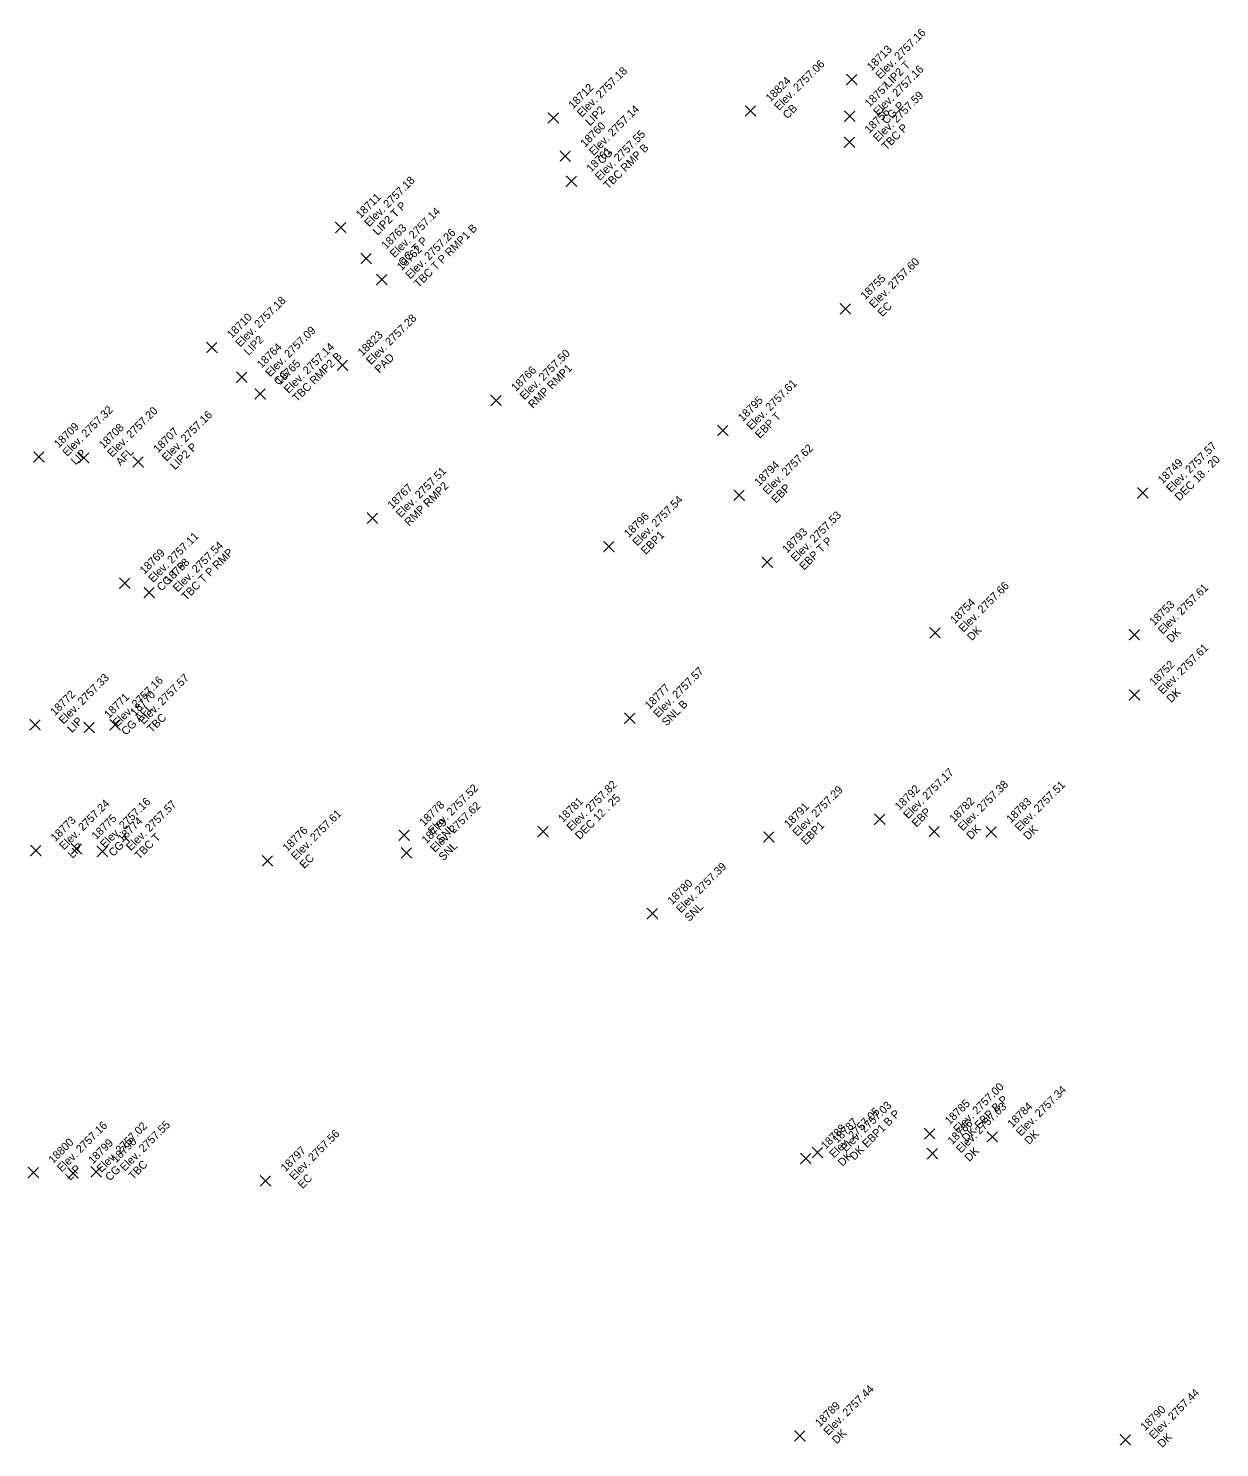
# Model space of a CAD drawing. Extents: x 2493999 to 2503109, y 700767 to 706646.
# Drawn here: x 2502305.46 to 2502341.16, y 700817.27 to 700859.84 of the extents above; entities that cross this region are included whole.
import ezdxf

# ---------------------------------------------------------------- set-up
doc = ezdxf.new("R2010")
doc.units = 0
doc.layers.add('ALG_CL_BLUE_Horiz', color=7, linetype='Continuous')
doc.layers.add('DES_SURFACE_Existing-Ground', color=7, linetype='Continuous')

msp = doc.modelspace()

# ---------------------------------------------------------------- linework, layer by layer
at = {"layer": 'ALG_CL_BLUE_Horiz'}
for points in [[(2502330.138, 700858.3), (2502329.988, 700858.45), (2502330.138, 700858.3), (2502329.988, 700858.15), (2502330.138, 700858.3), (2502330.288, 700858.15), (2502330.138, 700858.3), (2502330.288, 700858.45)], [(2502327.106, 700857.359), (2502326.956, 700857.509), (2502327.106, 700857.359), (2502326.956, 700857.209), (2502327.106, 700857.359), (2502327.256, 700857.209), (2502327.106, 700857.359), (2502327.256, 700857.509)], [(2502321.192, 700857.152), (2502321.042, 700857.302), (2502321.192, 700857.152), (2502321.042, 700857.002), (2502321.192, 700857.152), (2502321.342, 700857.002), (2502321.192, 700857.152), (2502321.342, 700857.302)], [(2502330.076, 700857.2), (2502329.926, 700857.35), (2502330.076, 700857.2), (2502329.926, 700857.05), (2502330.076, 700857.2), (2502330.226, 700857.05), (2502330.076, 700857.2), (2502330.226, 700857.35)], [(2502330.069, 700856.42), (2502329.919, 700856.57), (2502330.069, 700856.42), (2502329.919, 700856.27), (2502330.069, 700856.42), (2502330.219, 700856.27), (2502330.069, 700856.42), (2502330.219, 700856.57)], [(2502321.551, 700856.005), (2502321.401, 700856.155), (2502321.551, 700856.005), (2502321.401, 700855.855), (2502321.551, 700856.005), (2502321.701, 700855.855), (2502321.551, 700856.005), (2502321.701, 700856.155)], [(2502321.734, 700855.253), (2502321.584, 700855.403), (2502321.734, 700855.253), (2502321.584, 700855.103), (2502321.734, 700855.253), (2502321.884, 700855.103), (2502321.734, 700855.253), (2502321.884, 700855.403)], [(2502314.821, 700853.869), (2502314.671, 700854.019), (2502314.821, 700853.869), (2502314.671, 700853.719), (2502314.821, 700853.869), (2502314.971, 700853.719), (2502314.821, 700853.869), (2502314.971, 700854.019)], [(2502315.586, 700852.94), (2502315.436, 700853.09), (2502315.586, 700852.94), (2502315.436, 700852.79), (2502315.586, 700852.94), (2502315.736, 700852.79), (2502315.586, 700852.94), (2502315.736, 700853.09)], [(2502316.049, 700852.301), (2502315.899, 700852.451), (2502316.049, 700852.301), (2502315.899, 700852.151), (2502316.049, 700852.301), (2502316.199, 700852.151), (2502316.049, 700852.301), (2502316.199, 700852.451)], [(2502329.947, 700851.429), (2502329.797, 700851.579), (2502329.947, 700851.429), (2502329.797, 700851.279), (2502329.947, 700851.429), (2502330.097, 700851.279), (2502329.947, 700851.429), (2502330.097, 700851.579)], [(2502310.956, 700850.266), (2502310.806, 700850.416), (2502310.956, 700850.266), (2502310.806, 700850.116), (2502310.956, 700850.266), (2502311.106, 700850.116), (2502310.956, 700850.266), (2502311.106, 700850.416)], [(2502314.876, 700849.734), (2502314.726, 700849.884), (2502314.876, 700849.734), (2502314.726, 700849.584), (2502314.876, 700849.734), (2502315.026, 700849.584), (2502314.876, 700849.734), (2502315.026, 700849.884)], [(2502311.851, 700849.372), (2502311.701, 700849.522), (2502311.851, 700849.372), (2502311.701, 700849.222), (2502311.851, 700849.372), (2502312.001, 700849.222), (2502311.851, 700849.372), (2502312.001, 700849.522)], [(2502312.409, 700848.873), (2502312.259, 700849.023), (2502312.409, 700848.873), (2502312.259, 700848.723), (2502312.409, 700848.873), (2502312.559, 700848.723), (2502312.409, 700848.873), (2502312.559, 700849.023)], [(2502319.478, 700848.679), (2502319.328, 700848.829), (2502319.478, 700848.679), (2502319.328, 700848.529), (2502319.478, 700848.679), (2502319.628, 700848.529), (2502319.478, 700848.679), (2502319.628, 700848.829)], [(2502326.274, 700847.777), (2502326.124, 700847.927), (2502326.274, 700847.777), (2502326.124, 700847.627), (2502326.274, 700847.777), (2502326.424, 700847.627), (2502326.274, 700847.777), (2502326.424, 700847.927)], [(2502305.77, 700846.985), (2502305.62, 700847.135), (2502305.77, 700846.985), (2502305.62, 700846.835), (2502305.77, 700846.985), (2502305.92, 700846.835), (2502305.77, 700846.985), (2502305.92, 700847.135)], [(2502307.116, 700846.957), (2502306.966, 700847.107), (2502307.116, 700846.957), (2502306.966, 700846.807), (2502307.116, 700846.957), (2502307.266, 700846.807), (2502307.116, 700846.957), (2502307.266, 700847.107)], [(2502308.75, 700846.836), (2502308.6, 700846.986), (2502308.75, 700846.836), (2502308.6, 700846.686), (2502308.75, 700846.836), (2502308.9, 700846.686), (2502308.75, 700846.836), (2502308.9, 700846.986)], [(2502326.763, 700845.834), (2502326.613, 700845.984), (2502326.763, 700845.834), (2502326.613, 700845.684), (2502326.763, 700845.834), (2502326.913, 700845.684), (2502326.763, 700845.834), (2502326.913, 700845.984)], [(2502338.858, 700845.904), (2502338.708, 700846.054), (2502338.858, 700845.904), (2502338.708, 700845.754), (2502338.858, 700845.904), (2502339.008, 700845.754), (2502338.858, 700845.904), (2502339.008, 700846.054)], [(2502315.768, 700845.149), (2502315.618, 700845.299), (2502315.768, 700845.149), (2502315.618, 700844.999), (2502315.768, 700845.149), (2502315.918, 700844.999), (2502315.768, 700845.149), (2502315.918, 700845.299)], [(2502322.857, 700844.295), (2502322.707, 700844.445), (2502322.857, 700844.295), (2502322.707, 700844.145), (2502322.857, 700844.295), (2502323.007, 700844.145), (2502322.857, 700844.295), (2502323.007, 700844.445)], [(2502327.603, 700843.826), (2502327.453, 700843.976), (2502327.603, 700843.826), (2502327.453, 700843.676), (2502327.603, 700843.826), (2502327.753, 700843.676), (2502327.603, 700843.826), (2502327.753, 700843.976)], [(2502308.343, 700843.196), (2502308.193, 700843.346), (2502308.343, 700843.196), (2502308.193, 700843.046), (2502308.343, 700843.196), (2502308.493, 700843.046), (2502308.343, 700843.196), (2502308.493, 700843.346)], [(2502309.081, 700842.917), (2502308.931, 700843.067), (2502309.081, 700842.917), (2502308.931, 700842.767), (2502309.081, 700842.917), (2502309.231, 700842.767), (2502309.081, 700842.917), (2502309.231, 700843.067)], [(2502332.635, 700841.709), (2502332.485, 700841.859), (2502332.635, 700841.709), (2502332.485, 700841.559), (2502332.635, 700841.709), (2502332.785, 700841.559), (2502332.635, 700841.709), (2502332.785, 700841.859)], [(2502338.608, 700841.65), (2502338.458, 700841.8), (2502338.608, 700841.65), (2502338.458, 700841.5), (2502338.608, 700841.65), (2502338.758, 700841.5), (2502338.608, 700841.65), (2502338.758, 700841.8)], [(2502338.609, 700839.848), (2502338.459, 700839.998), (2502338.609, 700839.848), (2502338.459, 700839.698), (2502338.609, 700839.848), (2502338.759, 700839.698), (2502338.609, 700839.848), (2502338.759, 700839.998)], [(2502323.481, 700839.148), (2502323.331, 700839.298), (2502323.481, 700839.148), (2502323.331, 700838.998), (2502323.481, 700839.148), (2502323.631, 700838.998), (2502323.481, 700839.148), (2502323.631, 700839.298)], [(2502305.658, 700838.954), (2502305.508, 700839.104), (2502305.658, 700838.954), (2502305.508, 700838.804), (2502305.658, 700838.954), (2502305.808, 700838.804), (2502305.658, 700838.954), (2502305.808, 700839.104)], [(2502307.279, 700838.873), (2502307.129, 700839.023), (2502307.279, 700838.873), (2502307.129, 700838.723), (2502307.279, 700838.873), (2502307.429, 700838.723), (2502307.279, 700838.873), (2502307.429, 700839.023)], [(2502308.056, 700838.947), (2502307.906, 700839.097), (2502308.056, 700838.947), (2502307.906, 700838.797), (2502308.056, 700838.947), (2502308.206, 700838.797), (2502308.056, 700838.947), (2502308.206, 700839.097)], [(2502330.975, 700836.116), (2502330.825, 700836.266), (2502330.975, 700836.116), (2502330.825, 700835.966), (2502330.975, 700836.116), (2502331.125, 700835.966), (2502330.975, 700836.116), (2502331.125, 700836.266)], [(2502316.722, 700835.64), (2502316.572, 700835.79), (2502316.722, 700835.64), (2502316.572, 700835.49), (2502316.722, 700835.64), (2502316.872, 700835.49), (2502316.722, 700835.64), (2502316.872, 700835.79)], [(2502320.883, 700835.747), (2502320.733, 700835.897), (2502320.883, 700835.747), (2502320.733, 700835.597), (2502320.883, 700835.747), (2502321.033, 700835.597), (2502320.883, 700835.747), (2502321.033, 700835.897)], [(2502332.61, 700835.751), (2502332.46, 700835.901), (2502332.61, 700835.751), (2502332.46, 700835.601), (2502332.61, 700835.751), (2502332.76, 700835.601), (2502332.61, 700835.751), (2502332.76, 700835.901)], [(2502334.318, 700835.736), (2502334.168, 700835.886), (2502334.318, 700835.736), (2502334.168, 700835.586), (2502334.318, 700835.736), (2502334.468, 700835.586), (2502334.318, 700835.736), (2502334.468, 700835.886)], [(2502305.675, 700835.18), (2502305.525, 700835.33), (2502305.675, 700835.18), (2502305.525, 700835.03), (2502305.675, 700835.18), (2502305.825, 700835.03), (2502305.675, 700835.18), (2502305.825, 700835.33)], [(2502306.9, 700835.235), (2502306.75, 700835.385), (2502306.9, 700835.235), (2502306.75, 700835.085), (2502306.9, 700835.235), (2502307.05, 700835.085), (2502306.9, 700835.235), (2502307.05, 700835.385)], [(2502327.654, 700835.588), (2502327.504, 700835.738), (2502327.654, 700835.588), (2502327.504, 700835.438), (2502327.654, 700835.588), (2502327.804, 700835.438), (2502327.654, 700835.588), (2502327.804, 700835.738)], [(2502307.677, 700835.153), (2502307.527, 700835.303), (2502307.677, 700835.153), (2502307.527, 700835.003), (2502307.677, 700835.153), (2502307.827, 700835.003), (2502307.677, 700835.153), (2502307.827, 700835.303)], [(2502312.625, 700834.873), (2502312.475, 700835.023), (2502312.625, 700834.873), (2502312.475, 700834.723), (2502312.625, 700834.873), (2502312.775, 700834.723), (2502312.625, 700834.873), (2502312.775, 700835.023)], [(2502316.792, 700835.111), (2502316.642, 700835.261), (2502316.792, 700835.111), (2502316.642, 700834.961), (2502316.792, 700835.111), (2502316.942, 700834.961), (2502316.792, 700835.111), (2502316.942, 700835.261)], [(2502324.163, 700833.288), (2502324.013, 700833.438), (2502324.163, 700833.288), (2502324.013, 700833.138), (2502324.163, 700833.288), (2502324.313, 700833.138), (2502324.163, 700833.288), (2502324.313, 700833.438)], [(2502332.477, 700826.683), (2502332.327, 700826.833), (2502332.477, 700826.683), (2502332.327, 700826.533), (2502332.477, 700826.683), (2502332.627, 700826.533), (2502332.477, 700826.683), (2502332.627, 700826.833)], [(2502334.351, 700826.597), (2502334.201, 700826.747), (2502334.351, 700826.597), (2502334.201, 700826.447), (2502334.351, 700826.597), (2502334.501, 700826.447), (2502334.351, 700826.597), (2502334.501, 700826.747)], [(2502328.758, 700825.942), (2502328.608, 700826.092), (2502328.758, 700825.942), (2502328.608, 700825.792), (2502328.758, 700825.942), (2502328.908, 700825.792), (2502328.758, 700825.942), (2502328.908, 700826.092)], [(2502329.113, 700826.127), (2502328.963, 700826.277), (2502329.113, 700826.127), (2502328.963, 700825.977), (2502329.113, 700826.127), (2502329.263, 700825.977), (2502329.113, 700826.127), (2502329.263, 700826.277)], [(2502332.557, 700826.088), (2502332.407, 700826.238), (2502332.557, 700826.088), (2502332.407, 700825.938), (2502332.557, 700826.088), (2502332.707, 700825.938), (2502332.557, 700826.088), (2502332.707, 700826.238)], [(2502305.607, 700825.522), (2502305.457, 700825.672), (2502305.607, 700825.522), (2502305.457, 700825.372), (2502305.607, 700825.522), (2502305.757, 700825.372), (2502305.607, 700825.522), (2502305.757, 700825.672)], [(2502306.795, 700825.504), (2502306.645, 700825.654), (2502306.795, 700825.504), (2502306.645, 700825.354), (2502306.795, 700825.504), (2502306.945, 700825.354), (2502306.795, 700825.504), (2502306.945, 700825.654)], [(2502307.491, 700825.545), (2502307.341, 700825.695), (2502307.491, 700825.545), (2502307.341, 700825.395), (2502307.491, 700825.545), (2502307.641, 700825.395), (2502307.491, 700825.545), (2502307.641, 700825.695)], [(2502312.568, 700825.276), (2502312.418, 700825.426), (2502312.568, 700825.276), (2502312.418, 700825.126), (2502312.568, 700825.276), (2502312.718, 700825.126), (2502312.568, 700825.276), (2502312.718, 700825.426)], [(2502328.583, 700817.621), (2502328.433, 700817.771), (2502328.583, 700817.621), (2502328.433, 700817.471), (2502328.583, 700817.621), (2502328.733, 700817.471), (2502328.583, 700817.621), (2502328.733, 700817.771)], [(2502338.34, 700817.508), (2502338.19, 700817.658), (2502338.34, 700817.508), (2502338.19, 700817.358), (2502338.34, 700817.508), (2502338.49, 700817.358), (2502338.34, 700817.508), (2502338.49, 700817.658)]]:
    msp.add_lwpolyline(points, dxfattribs=at)

# ---------------------------------------------------------------- texts
at = {"layer": 'DES_SURFACE_Existing-Ground'}
for s, p in [('Elev. 2757.16', (2502330.987, 700858.3)), ('18713', (2502330.732, 700858.555)), ('Elev. 2757.06', (2502327.955, 700857.359)), ('Elev. 2757.16', (2502330.925, 700857.2)), ('LIP2 T', (2502331.241, 700858.045)), ('Elev. 2757.18', (2502322.041, 700857.152)), ('18824', (2502327.7, 700857.614)), ('18712', (2502321.786, 700857.407)), ('18757', (2502330.67, 700857.455)), ('Elev. 2757.59', (2502330.918, 700856.42)), ('LIP2', (2502322.295, 700856.897)), ('Elev. 2757.14', (2502322.4, 700856.005)), ('CB', (2502328.209, 700857.104)), ('18756', (2502330.663, 700856.675)), ('CG P', (2502331.179, 700856.945)), ('18760', (2502322.145, 700856.26)), ('Elev. 2757.55', (2502322.583, 700855.253)), ('TBC P', (2502331.172, 700856.165)), ('18761', (2502322.328, 700855.508)), ('CG', (2502322.654, 700855.75)), ('TBC RMP B', (2502322.837, 700854.998)), ('Elev. 2757.18', (2502315.67, 700853.869)), ('18711', (2502315.415, 700854.124)), ('LIP2 T P', (2502315.924, 700853.614)), ('Elev. 2757.14', (2502316.435, 700852.94)), ('18763', (2502316.18, 700853.195)), ('Elev. 2757.26', (2502316.898, 700852.301)), ('TBC T P RMP1 B', (2502317.152, 700852.046)), ('18762', (2502316.643, 700852.556)), ('CG T P', (2502316.689, 700852.685)), ('Elev. 2757.60', (2502330.796, 700851.429)), ('18755', (2502330.541, 700851.684)), ('Elev. 2757.18', (2502311.805, 700850.266)), ('EC', (2502331.05, 700851.174)), ('18710', (2502311.55, 700850.521)), ('Elev. 2757.28', (2502315.725, 700849.734)), ('Elev. 2757.09', (2502312.7, 700849.372)), ('18823', (2502315.47, 700849.989)), ('LIP2', (2502312.059, 700850.011)), ('18764', (2502312.445, 700849.627)), ('Elev. 2757.14', (2502313.258, 700848.873)), ('18765', (2502313.003, 700849.128)), ('TBC RMP2 B', (2502313.512, 700848.618)), ('PAD', (2502315.979, 700849.479)), ('Elev. 2757.50', (2502320.327, 700848.679)), ('CG', (2502312.954, 700849.117)), ('18766', (2502320.072, 700848.934)), ('RMP RMP1', (2502320.581, 700848.424)), ('Elev. 2757.61', (2502327.123, 700847.777)), ('18795', (2502326.868, 700848.032)), ('Elev. 2757.32', (2502306.619, 700846.985)), ('Elev. 2757.20', (2502307.965, 700846.957)), ('Elev. 2757.16', (2502309.599, 700846.836)), ('EBP T', (2502327.377, 700847.522)), ('18709', (2502306.364, 700847.24)), ('18708', (2502307.71, 700847.212)), ('18707', (2502309.344, 700847.091)), ('LIP2 P', (2502309.853, 700846.581)), ('Elev. 2757.62', (2502327.612, 700845.834)), ('Elev. 2757.57', (2502339.707, 700845.904)), ('LIP', (2502306.873, 700846.73)), ('AFL', (2502308.219, 700846.702)), ('18794', (2502327.357, 700846.089)), ('18749', (2502339.452, 700846.159)), ('DEC 18 . 20', (2502339.961, 700845.649)), ('Elev. 2757.51', (2502316.617, 700845.149)), ('18767', (2502316.362, 700845.404)), ('RMP RMP2', (2502316.871, 700844.894)), ('EBP', (2502327.866, 700845.579)), ('Elev. 2757.54', (2502323.706, 700844.295)), ('18796', (2502323.451, 700844.55)), ('Elev. 2757.53', (2502328.452, 700843.826)), ('Elev. 2757.11', (2502309.192, 700843.196)), ('EBP1', (2502323.96, 700844.04)), ('18793', (2502328.197, 700844.081)), ('Elev. 2757.54', (2502309.93, 700842.917)), ('EBP T P', (2502328.706, 700843.571)), ('18769', (2502308.937, 700843.451)), ('CG T P', (2502309.446, 700842.941)), ('18768', (2502309.675, 700843.172)), ('TBC T P RMP', (2502310.184, 700842.662)), ('Elev. 2757.66', (2502333.484, 700841.709)), ('Elev. 2757.61', (2502339.457, 700841.65)), ('18754', (2502333.229, 700841.964)), ('18753', (2502339.202, 700841.905)), ('DK', (2502333.738, 700841.454)), ('DK', (2502339.711, 700841.395)), ('Elev. 2757.61', (2502339.458, 700839.848)), ('18752', (2502339.203, 700840.103)), ('Elev. 2757.33', (2502306.507, 700838.954)), ('Elev. 2757.57', (2502308.905, 700838.947)), ('Elev. 2757.57', (2502324.33, 700839.148)), ('Elev. 2757.16', (2502308.128, 700838.873)), ('18777', (2502324.075, 700839.403)), ('DK', (2502339.712, 700839.593)), ('18772', (2502306.252, 700839.209)), ('18771', (2502307.873, 700839.128)), ('18770', (2502308.65, 700839.202)), ('SNL B', (2502324.584, 700838.893)), ('LIP', (2502306.761, 700838.699)), ('CG AFL', (2502308.382, 700838.618)), ('TBC', (2502309.159, 700838.692)), ('Elev. 2757.17', (2502331.824, 700836.116)), ('Elev. 2757.52', (2502317.571, 700835.64)), ('Elev. 2757.82', (2502321.732, 700835.747)), ('Elev. 2757.29', (2502328.503, 700835.588)), ('18792', (2502331.569, 700836.371)), ('Elev. 2757.38', (2502333.459, 700835.751)), ('Elev. 2757.51', (2502335.167, 700835.736)), ('Elev. 2757.24', (2502306.524, 700835.18)), ('Elev. 2757.16', (2502307.749, 700835.235)), ('Elev. 2757.57', (2502308.526, 700835.153)), ('18778', (2502317.316, 700835.895)), ('Elev. 2757.62', (2502317.641, 700835.111)), ('18781', (2502321.477, 700836.002)), ('DEC 12 . 25', (2502321.986, 700835.492)), ('18791', (2502328.248, 700835.843)), ('18782', (2502333.204, 700836.006)), ('18783', (2502334.912, 700835.991)), ('18773', (2502306.269, 700835.435)), ('18775', (2502307.494, 700835.49)), ('18774', (2502308.271, 700835.408)), ('Elev. 2757.61', (2502313.474, 700834.873)), ('EBP', (2502332.078, 700835.861)), ('18776', (2502313.219, 700835.128)), ('18779', (2502317.386, 700835.366)), ('SNL', (2502317.825, 700835.385)), ('EBP1', (2502328.757, 700835.333)), ('DK', (2502333.713, 700835.496)), ('DK', (2502335.421, 700835.481)), ('LIP', (2502306.778, 700834.925)), ('CG T', (2502308.003, 700834.98)), ('TBC T', (2502308.78, 700834.898)), ('SNL', (2502317.895, 700834.856)), ('EC', (2502313.728, 700834.618)), ('Elev. 2757.39', (2502325.012, 700833.288)), ('18780', (2502324.757, 700833.543)), ('SNL', (2502325.266, 700833.033)), ('Elev. 2757.00', (2502333.326, 700826.683)), ('Elev. 2757.34', (2502335.2, 700826.597)), ('18785', (2502333.071, 700826.938)), ('DK EBP B P', (2502333.58, 700826.428)), ('Elev. 2757.05', (2502329.607, 700825.942)), ('Elev. 2757.03', (2502329.962, 700826.127)), ('DK EBP1 B P', (2502330.216, 700825.872)), ('Elev. 2757.03', (2502333.406, 700826.088)), ('18784', (2502334.945, 700826.852)), ('Elev. 2757.16', (2502306.456, 700825.522)), ('Elev. 2757.02', (2502307.644, 700825.504)), ('Elev. 2757.55', (2502308.34, 700825.545)), ('Elev. 2757.56', (2502313.417, 700825.276)), ('18788', (2502329.352, 700826.197)), ('18787', (2502329.707, 700826.382)), ('18786', (2502333.151, 700826.343)), ('DK', (2502335.454, 700826.342)), ('18800', (2502306.201, 700825.777)), ('18799', (2502307.389, 700825.759)), ('18798', (2502308.085, 700825.8)), ('18797', (2502313.162, 700825.531)), ('DK', (2502329.861, 700825.687)), ('DK', (2502333.66, 700825.833)), ('LIP', (2502306.71, 700825.267)), ('CG', (2502307.898, 700825.249)), ('TBC', (2502308.594, 700825.29)), ('EC', (2502313.671, 700825.021)), ('Elev. 2757.44', (2502329.432, 700817.621)), ('Elev. 2757.44', (2502339.189, 700817.508)), ('18789', (2502329.177, 700817.876)), ('18790', (2502338.934, 700817.763)), ('DK', (2502329.686, 700817.366)), ('DK', (2502339.443, 700817.253))]:
    msp.add_text(s, height=0.24, rotation=45, dxfattribs=at).set_placement(p)

doc.saveas('drawing.dxf')
